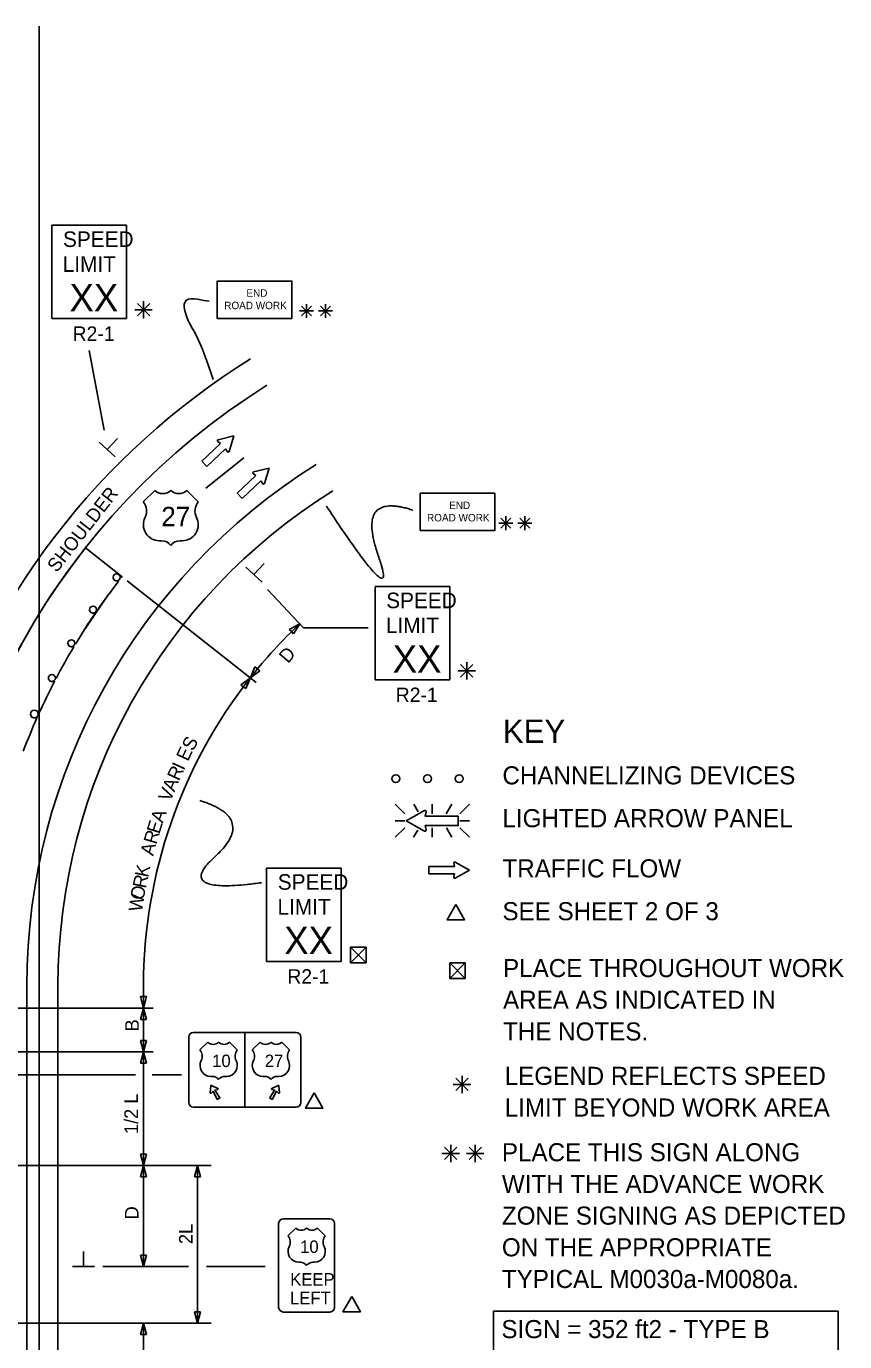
# Model space of a CAD drawing. Extents: x 16512 to 19509, y 5761 to 6974.
# Drawn here: x 16998 to 17419, y 6297 to 6974 of the extents above; entities that cross this region are included whole.
import ezdxf

# ---------------------------------------------------------------- set-up
doc = ezdxf.new("R2010")
doc.units = 0
for name, color, linetype in [('ALI_LEGAL_EX', 7, 'Continuous'), ('MT_SCRATCH_LEVEL_A', 7, 'Continuous'), ('MT_SCRATCH_LEVEL_E', 7, 'Continuous'), ('PAVT_EDGE_EX', 7, 'Continuous'), ('TRAFFIC_SIGNS_PR', 7, 'Continuous'), ('TYPICAL_EX', 7, 'Continuous'), ('TYPICAL_TEXT_DIMEN_EX', 7, 'Continuous'), ('TYPICAL_TEXT_DIMEN_PR', 7, 'Continuous')]:
    doc.layers.add(name, color=color, linetype=linetype)

msp = doc.modelspace()

# ---------------------------------------------------------------- linework, layer by layer
at = {"layer": 'ALI_LEGAL_EX'}
for p, q in [((17004.68, 6974.12), (17004.68, 6155.98)), ((17004.68, 6922.21), (17004.68, 6058.3))]:
    msp.add_line(p, q, dxfattribs=at)
for points in [[(17004.68, 6949.12), (17004.68, 6974.12)], [(17090.52, 6736.48), (17109.97, 6752.18)], [(17026.51, 6661.47), (17040.64, 6682.1)]]:
    msp.add_lwpolyline(points, dxfattribs=at)
at = {"layer": 'MT_SCRATCH_LEVEL_A'}
for points in [[(17047.4, 6690.98), (17028.55, 6705.83)], [(17045.52, 6688.56), (17045.06, 6688.91)], [(17046.41, 6690.77), (17047.26, 6690.79)], [(17033.55, 6672.09), (17033.12, 6672.38)], [(17034.27, 6674.06), (17034.69, 6673.76)], [(17022.59, 6654.94), (17022.2, 6655.17)], [(17023.15, 6656.76), (17023.54, 6656.52)], [(17013.08, 6638.82), (17013.44, 6638.63)], [(17012.67, 6637.16), (17012.32, 6637.35)], [(17003.81, 6618.76), (17003.65, 6618.83)], [(17004.31, 6620.31), (17004.48, 6620.24)]]:
    msp.add_lwpolyline(points, dxfattribs=at)
for centre, radius, start, end in [((17314.45, 6480.53), 364, 141.75977, 180), ((17044.61, 6690.66), 1.8, 3.5129, 180), ((17314.45, 6480.53), 340, 142.2759, 145.36613), ((17044.61, 6690.66), 1.8, 180, 284.5518), ((17314.45, 6480.53), 340, 141.75977, 141.79923), ((17314.45, 6480.53), 340, 145.70741, 148.82754), ((17032.47, 6674.06), 1.8, 0, 180), ((17032.47, 6674.06), 1.8, 180, 291.41483), ((17021.35, 6656.76), 1.8, 0, 180), ((17314.45, 6480.53), 340, 149.13833, 152.28953), ((17021.35, 6656.76), 1.8, 180, 298.27665), ((17011.28, 6638.82), 1.8, 0, 180), ((17011.28, 6638.82), 1.8, 180, 305.13736), ((17314.45, 6480.53), 340, 152.56868, 155.7382), ((17314.45, 6480.53), 340, 156.0121, 159.20322), ((17002.31, 6620.31), 2, 0, 180), ((17002.31, 6620.31), 2, 180, 312.02419)]:
    msp.add_arc(centre, radius, start, end, dxfattribs=at)
at = {"layer": 'MT_SCRATCH_LEVEL_E'}
for p, q in [((17096.59, 6760.6), (17098.04, 6759.51)), ((17104.85, 6763.37), (17096.76, 6761.41)), ((17102.41, 6755.39), (17104.85, 6763.37)), ((17098.04, 6759.51), (17088.37, 6750.45)), ((17090.92, 6747.72), (17100.6, 6756.78)), ((17100.6, 6756.78), (17101.58, 6755.27)), ((17088.37, 6750.45), (17090.92, 6747.72)), ((17123.06, 6746.9), (17114.96, 6744.94)), ((17120.61, 6738.92), (17123.06, 6746.9)), ((17116.24, 6743.04), (17106.57, 6733.98)), ((17109.13, 6731.25), (17118.8, 6740.31)), ((17114.79, 6744.12), (17116.24, 6743.04)), ((17118.8, 6740.31), (17119.78, 6738.8)), ((17106.57, 6733.98), (17109.13, 6731.25)), ((17218.08, 6543.71), (17218.4, 6541.94)), ((17226.01, 6540.09), (17218.77, 6544.2)), ((17218.4, 6541.94), (17205.14, 6541.94)), ((17205.14, 6541.94), (17205.14, 6538.19)), ((17205.14, 6538.19), (17218.4, 6538.19)), ((17218.4, 6538.19), (17218.08, 6536.42)), ((17218.77, 6535.94), (17226.01, 6540.09))]:
    msp.add_line(p, q, dxfattribs=at)
for centre, start, end in [((17096.87, 6760.96), 103.58205, 233.12102), ((17101.96, 6755.54), 213.1934, 342.93033), ((17115.08, 6744.49), 103.58205, 233.12102), ((17120.17, 6739.07), 213.1934, 342.93033), ((17218.54, 6543.79), 60.42484, 189.96381), ((17218.54, 6536.35), 170.03619, 299.77312)]:
    msp.add_arc(centre, 0.463, start, end, dxfattribs=at)
at = {"layer": 'PAVT_EDGE_EX'}
for p, q in [((16998.45, 6480.53), (16998.45, 6125.9)), ((17014.45, 6480.53), (17014.45, 6125.9))]:
    msp.add_line(p, q, dxfattribs=at)
for radius, start, end in [(380, 121.93275, 163.04831), (364, 121.93275, 180), (316, 121.93275, 180), (300, 121.93275, 180), (300, 180, 180.00000277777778)]:
    msp.add_arc((17314.45, 6480.53), radius, start, end, dxfattribs=at)
at = {"layer": 'TRAFFIC_SIGNS_PR'}
for p, q in [((17011.27, 6871.74), (17049.67, 6871.74)), ((17011.27, 6823.74), (17011.27, 6871.74)), ((17049.67, 6823.74), (17049.67, 6871.74)), ((17011.27, 6823.74), (17049.67, 6823.74)), ((17177.5, 6685.93), (17215.9, 6685.93)), ((17177.5, 6637.93), (17177.5, 6685.93)), ((17215.9, 6637.93), (17215.9, 6685.93)), ((17177.5, 6637.93), (17215.9, 6637.93)), ((17187.86, 6573.9), (17192.79, 6568.96)), ((17199.62, 6570.07), (17197.41, 6573.9)), ((17206.94, 6568.96), (17206.94, 6573.9)), ((17214.17, 6568.96), (17217.02, 6573.9)), ((17221.09, 6568.96), (17226.03, 6573.9)), ((17192.79, 6565.41), (17187.86, 6565.41)), ((17221.09, 6565.41), (17226.03, 6565.41)), ((17187.86, 6556.92), (17192.79, 6561.85)), ((17197.37, 6556.92), (17199.48, 6560.58)), ((17206.94, 6561.85), (17206.94, 6556.92)), ((17217.07, 6556.92), (17214.22, 6561.85)), ((17221.09, 6561.85), (17226.03, 6556.91)), ((17121.73, 6541.08), (17160.13, 6541.08)), ((17121.73, 6493.08), (17121.73, 6541.08)), ((17160.13, 6493.08), (17160.13, 6541.08)), ((17121.73, 6493.08), (17160.13, 6493.08)), ((17084.13, 6456.52), (17136.93, 6456.52)), ((17110.53, 6456.52), (17110.53, 6418.12)), ((17081.73, 6454.12), (17081.73, 6420.52)), ((17139.33, 6454.12), (17139.33, 6420.52)), ((17092.71, 6425.47), (17092.99, 6429.09)), ((17093.36, 6429.3), (17096.64, 6427.74)), ((17127.69, 6429.3), (17124.42, 6427.74)), ((17128.35, 6425.47), (17128.07, 6429.09)), ((17084.13, 6418.12), (17136.93, 6418.12)), ((17127.94, 6358.32), (17127.94, 6315.12)), ((17154.33, 6360.72), (17130.33, 6360.72)), ((17156.74, 6315.12), (17156.74, 6358.32)), ((17130.33, 6312.72), (17154.33, 6312.72))]:
    msp.add_line(p, q, dxfattribs=at)
for points in [[(17096.33, 6823.86), (17134.73, 6823.86), (17134.73, 6843.06), (17096.33, 6843.06)], [(17200.64, 6714.68), (17239.04, 6714.68), (17239.04, 6733.88), (17200.64, 6733.88)]]:
    msp.add_lwpolyline(points, close=True, dxfattribs=at)
for points in [[(17202.87, 6570.68), (17193.58, 6565.41), (17202.87, 6560.09)], [(17203.74, 6560.71), (17203.34, 6562.98), (17220.35, 6562.98), (17220.35, 6567.78), (17203.34, 6567.78), (17203.74, 6570.06)], [(17096.6, 6427.25), (17095.19, 6426.86), (17097.71, 6422.88), (17096.38, 6422.12), (17094.19, 6426.29), (17093.15, 6425.26)], [(17124.46, 6427.25), (17125.87, 6426.86), (17123.35, 6422.88), (17124.68, 6422.12), (17126.87, 6426.29), (17127.91, 6425.26)]]:
    msp.add_lwpolyline(points, dxfattribs=at)
for centre, radius in [((17044.61, 6690.66), 1.8), ((17032.47, 6674.06), 1.8), ((17021.35, 6656.76), 1.8), ((17011.28, 6638.82), 1.8), ((17002.31, 6620.31), 2), ((17188.2, 6587.09), 2), ((17204.5, 6587.09), 2), ((17220.8, 6587.09), 2)]:
    msp.add_circle(centre, radius, dxfattribs=at)
for centre, radius, start, end in [((17203.16, 6570.16), 0.598, 350.73078, 118.89165), ((17203.15, 6560.61), 0.597, 241.48329, 9.95933), ((17084.13, 6454.12), 2.4, 90, 180), ((17084.13, 6454.12), 2.4, 90, 180), ((17136.93, 6454.12), 2.4, 0, 90), ((17093.25, 6429.07), 0.26, 64.48226, 175.51774), ((17127.81, 6429.07), 0.26, 4.48226, 115.51774), ((17092.97, 6425.45), 0.26, 175.51775, 314.01151), ((17096.53, 6427.5), 0.26, 285.9885, 64.48226), ((17124.53, 6427.5), 0.26, 115.51774, 254.0115), ((17128.09, 6425.45), 0.26, 225.98849, 4.48225), ((17084.13, 6420.52), 2.4, 180, 270), ((17136.93, 6420.52), 2.4, 270, 0), ((17130.33, 6358.32), 2.4, 90, 180), ((17154.33, 6358.32), 2.4, 0, 90), ((17130.33, 6315.12), 2.4, 180, 270), ((17154.33, 6315.12), 2.4, 270, 0)]:
    msp.add_arc(centre, radius, start, end, dxfattribs=at)
at = {"layer": 'TYPICAL_EX'}
for p, q in [((17058.33, 6729.51), (17064.22, 6735.4)), ((17086.62, 6729.51), (17080.73, 6735.4)), ((17066.57, 6709.45), (17067.75, 6709.45)), ((17078.38, 6709.45), (17077.2, 6709.45)), ((17087.48, 6447.52), (17091.48, 6451.52)), ((17106.68, 6447.52), (17102.68, 6451.52)), ((17114.38, 6447.52), (17118.38, 6451.52)), ((17133.58, 6447.52), (17129.58, 6451.52)), ((17093.07, 6433.91), (17093.87, 6433.91)), ((17101.09, 6433.91), (17100.29, 6433.91)), ((17119.97, 6433.91), (17120.77, 6433.91)), ((17127.99, 6433.91), (17127.19, 6433.91)), ((17132.74, 6351.92), (17136.74, 6355.92)), ((17151.94, 6351.92), (17147.94, 6355.92)), ((17138.33, 6338.31), (17139.13, 6338.31)), ((17146.34, 6338.31), (17145.54, 6338.31))]:
    msp.add_line(p, q, dxfattribs=at)
for centre, radius, start, end in [((17068.35, 6739.69), 5.96, 226.14041, 313.85958), ((17076.6, 6739.69), 5.96, 226.14042, 313.85959), ((17052.74, 6724.78), 7.31, 333.09768, 40.19361), ((17092.21, 6724.78), 7.31, 139.80639, 206.90233), ((17066.59, 6717.69), 8.24, 152.6698, 269.90132), ((17078.36, 6717.69), 8.24, 270.09868, 27.3302), ((17067.77, 6703.54), 5.91, 37.1038, 90.13853), ((17077.19, 6703.54), 5.91, 89.86147, 142.8962), ((17094.28, 6454.43), 4.04, 226.14041, 313.85958), ((17099.88, 6454.43), 4.04, 226.14042, 313.85959), ((17121.18, 6454.43), 4.04, 226.14041, 313.85958), ((17126.78, 6454.43), 4.04, 226.14042, 313.85959), ((17083.69, 6444.31), 4.96, 333.09768, 40.19361), ((17093.08, 6439.5), 5.59, 152.6698, 269.90132), ((17101.08, 6439.5), 5.59, 270.09868, 27.3302), ((17110.47, 6444.31), 4.96, 139.80639, 206.90233), ((17110.59, 6444.31), 4.96, 333.09768, 40.19361), ((17119.98, 6439.5), 5.59, 152.6698, 269.90132), ((17127.97, 6439.5), 5.59, 270.09868, 27.3302), ((17137.37, 6444.31), 4.96, 139.80639, 206.90233), ((17093.88, 6429.9), 4.01, 37.1038, 90.13853), ((17100.28, 6429.9), 4.01, 89.86147, 142.8962), ((17120.78, 6429.9), 4.01, 37.1038, 90.13853), ((17127.17, 6429.9), 4.01, 89.86147, 142.8962), ((17139.54, 6358.83), 4.04, 226.14041, 313.85958), ((17145.13, 6358.83), 4.04, 226.14042, 313.85959), ((17128.94, 6348.71), 4.96, 333.09768, 40.19361), ((17155.73, 6348.71), 4.96, 139.80639, 206.90233), ((17138.34, 6343.9), 5.59, 152.6698, 269.90132), ((17146.33, 6343.9), 5.59, 270.09868, 27.3302), ((17139.14, 6334.3), 4.01, 37.1038, 90.13853), ((17145.53, 6334.3), 4.01, 89.86147, 142.8962)]:
    msp.add_arc(centre, radius, start, end, dxfattribs=at)
at = {"layer": 'TYPICAL_TEXT_DIMEN_EX'}
msp.add_lwpolyline([(17238.46, 6313.09), (17415.73, 6313.09), (17415.73, 6227.77), (17238.46, 6227.77)], close=True, dxfattribs=at)
at = {"layer": 'TYPICAL_TEXT_DIMEN_PR'}
for p, q in [((17058.46, 6828.35), (17053.93, 6828.35)), ((17061.65, 6831.54), (17055.27, 6825.16)), ((17055.28, 6831.54), (17061.65, 6825.16)), ((17058.46, 6828.35), (17058.46, 6832.81)), ((17058.46, 6828.35), (17061.65, 6828.35)), ((17058.46, 6828.35), (17062.94, 6828.35)), ((17058.46, 6828.35), (17058.46, 6823.85)), ((17142.28, 6827.68), (17138.66, 6827.68)), ((17139.73, 6830.23), (17144.83, 6825.13)), ((17144.83, 6830.23), (17139.73, 6825.13)), ((17142.28, 6827.68), (17142.28, 6831.24)), ((17142.28, 6827.68), (17144.83, 6827.68)), ((17142.28, 6827.68), (17145.87, 6827.68)), ((17142.28, 6827.68), (17142.28, 6824.08)), ((17152.03, 6827.68), (17148.4, 6827.68)), ((17149.48, 6830.23), (17154.58, 6825.13)), ((17154.58, 6830.23), (17149.48, 6825.13)), ((17152.03, 6827.68), (17152.03, 6831.24)), ((17152.03, 6827.68), (17154.58, 6827.68)), ((17152.03, 6827.68), (17155.61, 6827.68)), ((17152.03, 6827.68), (17152.03, 6824.08)), ((17038.28, 6766.41), (17030.49, 6807.29)), ((17043.83, 6752.57), (17035.58, 6760.22)), ((17039.7, 6756.39), (17045, 6762.1)), ((17242.2, 6721.05), (17247.3, 6715.95)), ((17247.3, 6721.05), (17242.2, 6715.95)), ((17244.75, 6718.5), (17244.75, 6722.06)), ((17251.94, 6721.05), (17257.04, 6715.95)), ((17257.04, 6721.05), (17251.94, 6715.95)), ((17254.49, 6718.5), (17254.49, 6722.06)), ((17244.75, 6718.5), (17241.12, 6718.5)), ((17244.75, 6718.5), (17247.3, 6718.5)), ((17244.75, 6718.5), (17248.33, 6718.5)), ((17244.75, 6718.5), (17244.75, 6714.9)), ((17254.49, 6718.5), (17250.87, 6718.5)), ((17254.49, 6718.5), (17257.04, 6718.5)), ((17254.49, 6718.5), (17258.08, 6718.5)), ((17254.49, 6718.5), (17254.49, 6714.9)), ((17119.38, 6688.23), (17111.13, 6695.89)), ((17115.25, 6692.06), (17120.55, 6697.77)), ((17050.11, 6688.84), (17116.38, 6636.62)), ((17122.13, 6684.37), (17140.75, 6664.64)), ((17133.42, 6663.86), (17138.77, 6666.74)), ((17138.77, 6666.74), (17135.58, 6661.57)), ((17134.5, 6662.71), (17133.42, 6663.86)), ((17135.58, 6661.57), (17134.5, 6662.71)), ((17140.75, 6664.64), (17173.95, 6664.64)), ((17221.5, 6645.73), (17227.87, 6639.36)), ((17227.87, 6645.73), (17221.5, 6639.36)), ((17224.69, 6642.55), (17224.69, 6647)), ((17108.52, 6635.35), (17113.38, 6638.99)), ((17113.38, 6638.99), (17110.98, 6633.41)), ((17113.38, 6638.99), (17115.77, 6644.56)), ((17118.24, 6642.62), (17113.38, 6638.99)), ((17115.77, 6644.56), (17117.01, 6643.59)), ((17117.01, 6643.59), (17118.24, 6642.62)), ((17224.69, 6642.55), (17220.15, 6642.55)), ((17224.69, 6642.55), (17227.87, 6642.55)), ((17224.69, 6642.55), (17229.16, 6642.55)), ((17224.69, 6642.55), (17224.69, 6638.05)), ((17109.75, 6634.38), (17108.52, 6635.35)), ((17110.98, 6633.41), (17109.75, 6634.38)), ((17004.96, 6621.31), (17003.13, 6622.14)), ((17164.92, 6500.4), (17172.92, 6492.4)), ((17164.92, 6492.4), (17172.92, 6500.4)), ((17215.92, 6492.31), (17223.92, 6484.31)), ((17215.92, 6484.31), (17223.92, 6492.31)), ((17058.45, 6480.53), (17058.45, 6469.09)), ((16977.64, 6469.09), (17063.45, 6469.09)), ((17058.45, 6469.09), (17056.88, 6474.95)), ((17056.88, 6474.95), (17058.45, 6474.95)), ((17056.88, 6463.22), (17058.45, 6469.09)), ((17058.45, 6474.95), (17060.02, 6474.95)), ((17060.02, 6474.95), (17058.45, 6469.09)), ((17058.45, 6469.09), (17058.45, 6446.53)), ((17058.45, 6469.09), (17060.02, 6463.22)), ((17058.45, 6463.22), (17056.88, 6463.22)), ((17060.02, 6463.22), (17058.45, 6463.22)), ((17058.45, 6446.53), (17056.88, 6452.39)), ((17056.88, 6452.39), (17058.45, 6452.39)), ((17058.45, 6452.39), (17060.02, 6452.39)), ((17060.02, 6452.39), (17058.45, 6446.53)), ((16977.64, 6446.53), (17063.45, 6446.53)), ((17056.88, 6440.67), (17058.45, 6446.53)), ((17058.45, 6446.53), (17058.45, 6388.14)), ((17058.45, 6446.53), (17060.02, 6440.67)), ((17058.45, 6440.67), (17056.88, 6440.67)), ((17060.02, 6440.67), (17058.45, 6440.67)), ((17054.35, 6434.68), (16990.46, 6434.68)), ((17062.85, 6434.68), (17078.05, 6434.68)), ((17222.3, 6429.82), (17217.76, 6429.82)), ((17219.11, 6433.01), (17225.48, 6426.64)), ((17225.48, 6433.01), (17219.11, 6426.64)), ((17222.3, 6429.82), (17222.3, 6434.28)), ((17222.3, 6429.82), (17225.48, 6429.82)), ((17222.3, 6429.82), (17226.77, 6429.82)), ((17222.3, 6429.82), (17222.3, 6425.32)), ((17213.28, 6397.51), (17219.66, 6391.13)), ((17219.66, 6397.51), (17213.28, 6391.13)), ((17216.47, 6394.32), (17216.47, 6398.78)), ((17225.84, 6397.51), (17232.21, 6391.13)), ((17232.21, 6397.51), (17225.84, 6391.13)), ((17229.02, 6394.32), (17229.02, 6398.78)), ((17093.24, 6388.14), (16977.64, 6388.14)), ((17058.45, 6388.14), (17056.88, 6394)), ((17056.88, 6394), (17058.45, 6394)), ((17056.88, 6382.28), (17058.45, 6388.14)), ((17058.45, 6394), (17060.02, 6394)), ((17060.02, 6394), (17058.45, 6388.14)), ((17058.45, 6388.14), (17060.02, 6382.28)), ((17058.45, 6388.14), (17058.45, 6336.14)), ((17084.68, 6382.28), (17086.25, 6388.14)), ((17086.25, 6388.14), (17086.25, 6307.03)), ((17086.25, 6388.14), (17087.82, 6382.28)), ((17216.47, 6394.32), (17211.94, 6394.32)), ((17216.47, 6394.32), (17219.66, 6394.32)), ((17216.47, 6394.32), (17220.95, 6394.32)), ((17216.47, 6394.32), (17216.47, 6389.82)), ((17229.02, 6394.32), (17224.49, 6394.32)), ((17229.02, 6394.32), (17232.21, 6394.32)), ((17229.02, 6394.32), (17233.5, 6394.32)), ((17229.02, 6394.32), (17229.02, 6389.82)), ((17058.45, 6382.28), (17056.88, 6382.28)), ((17060.02, 6382.28), (17058.45, 6382.28)), ((17086.25, 6382.28), (17084.68, 6382.28)), ((17087.82, 6382.28), (17086.25, 6382.28)), ((17027.57, 6336.14), (17027.57, 6343.92)), ((17058.45, 6336.14), (17056.88, 6342)), ((17056.88, 6342), (17058.45, 6342)), ((17058.45, 6342), (17060.02, 6342)), ((17060.02, 6342), (17058.45, 6336.14)), ((17033.2, 6336.14), (17021.95, 6336.14)), ((17081.61, 6336.14), (17037.45, 6336.14)), ((17120.94, 6336.14), (17090.76, 6336.14)), ((16953.49, 6307.03), (17093.24, 6307.03)), ((17056.88, 6301.17), (17058.45, 6307.03)), ((17058.45, 6278.47), (17058.45, 6307.03)), ((17058.45, 6307.03), (17060.02, 6301.17)), ((17086.25, 6307.03), (17084.68, 6312.89)), ((17084.68, 6312.89), (17086.25, 6312.89)), ((17086.25, 6312.89), (17087.82, 6312.89)), ((17087.82, 6312.89), (17086.25, 6307.03)), ((17058.45, 6301.17), (17056.88, 6301.17)), ((17060.02, 6301.17), (17058.45, 6301.17))]:
    msp.add_line(p, q, dxfattribs=at)
for points in [[(17219.07, 6522.38), (17214.55, 6514.54), (17223.6, 6514.54)], [(17164.92, 6500.4), (17164.92, 6492.4), (17172.92, 6492.4), (17172.92, 6500.4)], [(17215.92, 6492.31), (17215.92, 6484.31), (17223.92, 6484.31), (17223.92, 6492.31)], [(17146.22, 6425.5), (17141.69, 6417.66), (17150.74, 6417.66)], [(17165.5, 6320.68), (17160.98, 6312.84), (17170.03, 6312.84)]]:
    msp.add_lwpolyline(points, close=True, dxfattribs=at)
for start, end in [(133.33402, 141.75968), (141.75968, 180)]:
    msp.add_arc((17314.45, 6480.53), 256, start, end, dxfattribs=at)
for points, degree in [([(17094.25, 6792.38), (17087.41, 6813.26), (17081.47, 6820.53), (17076.41, 6836.91), (17089.34, 6833), (17092.12, 6832.64)], 3), ([(17152.53, 6727.28), (17190.76, 6669.11), (17167.55, 6734.81), (17196.9, 6725.23)], 2), ([(17087.4, 6575.84), (17116.93, 6566.68), (17073.34, 6527.21), (17119.04, 6533.55)], 2)]:
    msp.add_open_spline(points, degree=degree, dxfattribs=at)

# ---------------------------------------------------------------- texts
at = {"layer": 'TRAFFIC_SIGNS_PR'}
for s, height, p in [('SPEED', 8, (17017.04, 6860.6)), ('LIMIT', 8, (17016.88, 6847.8)), ('XX', 14.031, (17020.39, 6827.49)), ('END', 3.831, (17111.34, 6834.99)), ('ROAD WORK', 3.831, (17099.94, 6828.6)), ('R2-1', 7.44, (17021.95, 6812.3)), ('END', 3.831, (17215.64, 6725.81)), ('ROAD WORK', 3.831, (17204.25, 6719.42)), ('SPEED', 8, (17183.26, 6674.79)), ('LIMIT', 8, (17183.1, 6661.99)), ('XX', 14.031, (17186.61, 6641.69)), ('R2-1', 7.44, (17188.17, 6626.49)), ('SPEED', 8, (17127.5, 6529.94)), ('LIMIT', 8, (17127.34, 6517.14)), ('XX', 14.031, (17130.84, 6496.84)), ('R2-1', 7.44, (17132.41, 6481.64)), ('10', 6.4, (17093.74, 6438.72)), ('27', 6.4, (17120.81, 6438.72)), ('10', 6.4, (17138.99, 6343.12)), ('KEEP', 6.4, (17133.87, 6326.32)), ('LEFT', 6.4, (17133.78, 6316.72))]:
    msp.add_text(s, height=height, dxfattribs=at).set_placement(p)
at = {"layer": 'TYPICAL_EX'}
msp.add_text('27', height=10, dxfattribs=at).set_placement((17067.59, 6716.93))
at = {"layer": 'TYPICAL_TEXT_DIMEN_EX'}
for s, height, p in [('KEY', 12, (17243.23, 6605.49)), ('CHANNELIZING DEVICES', 9.3, (17243.04, 6584.15)), ('LIGHTED ARROW PANEL', 9.3, (17243.04, 6562.1)), ('TRAFFIC FLOW', 9.3, (17243.04, 6536.3)), ('SEE SHEET 2 OF 3', 9.3, (17243.04, 6514.25)), ('PLACE THROUGHOUT WORK', 9.3, (17243.35, 6484.99)), ('AREA AS INDICATED IN', 9.3, (17243.35, 6468.69)), ('THE NOTES.', 9.3, (17243.35, 6452.39)), ('LEGEND REFLECTS SPEED', 9.3, (17244.2, 6429.56)), ('LIMIT BEYOND WORK AREA', 9.3, (17244.2, 6413.26)), ('PLACE THIS SIGN ALONG', 9.3, (17242.76, 6390.26)), ('WITH THE ADVANCE WORK', 9.3, (17242.76, 6373.96)), ('ZONE SIGNING AS DEPICTED', 9.3, (17242.76, 6357.66)), ('ON THE APPROPRIATE', 9.3, (17242.76, 6341.36)), ('TYPICAL M0030a-M0080a.', 9.3, (17242.76, 6325.06)), ('SIGN = 352 ft2 - TYPE B', 9.3, (17242.51, 6299.27))]:
    msp.add_text(s, height=height, dxfattribs=at).set_placement(p)
at = {"layer": 'TYPICAL_TEXT_DIMEN_PR'}
for s, rotation, p in [('SHOULDER', 52.01843, (17013.81, 6692.73)), ('D', 50, (17132.79, 6646.01)), ('S', 62.49737, (17083.98, 6600.91)), ('E', 65.17719, (17081.28, 6595.61)), ('R', 65.17719, (17076.62, 6585.54)), ('I', 65.17719, (17079.13, 6590.96)), ('A', 67.85702, (17074.34, 6579.94)), ('V', 67.85702, (17072.25, 6574.78)), ('E', 73.21667, (17066.62, 6558.32)), ('A', 70.53685, (17068.37, 6563.9)), ('R', 73.21667, (17064.99, 6552.92)), ('A', 75.8965, (17063.42, 6547.08)), ('R', 78.57633, (17059.63, 6530.32)), ('K', 78.57633, (17060.77, 6535.95)), ('O', 81.25615, (17058.54, 6524.36)), ('W', 81.25615, (17057.62, 6518.33)), ('B', 90, (17056.01, 6457.04)), ('1/2 L', 90, (17055.59, 6404.27)), ('D', 90, (17055.89, 6360.36)), ('2L', 90, (17083.69, 6347.64))]:
    msp.add_text(s, height=7, rotation=rotation, dxfattribs=at).set_placement(p)

doc.saveas('drawing.dxf')
